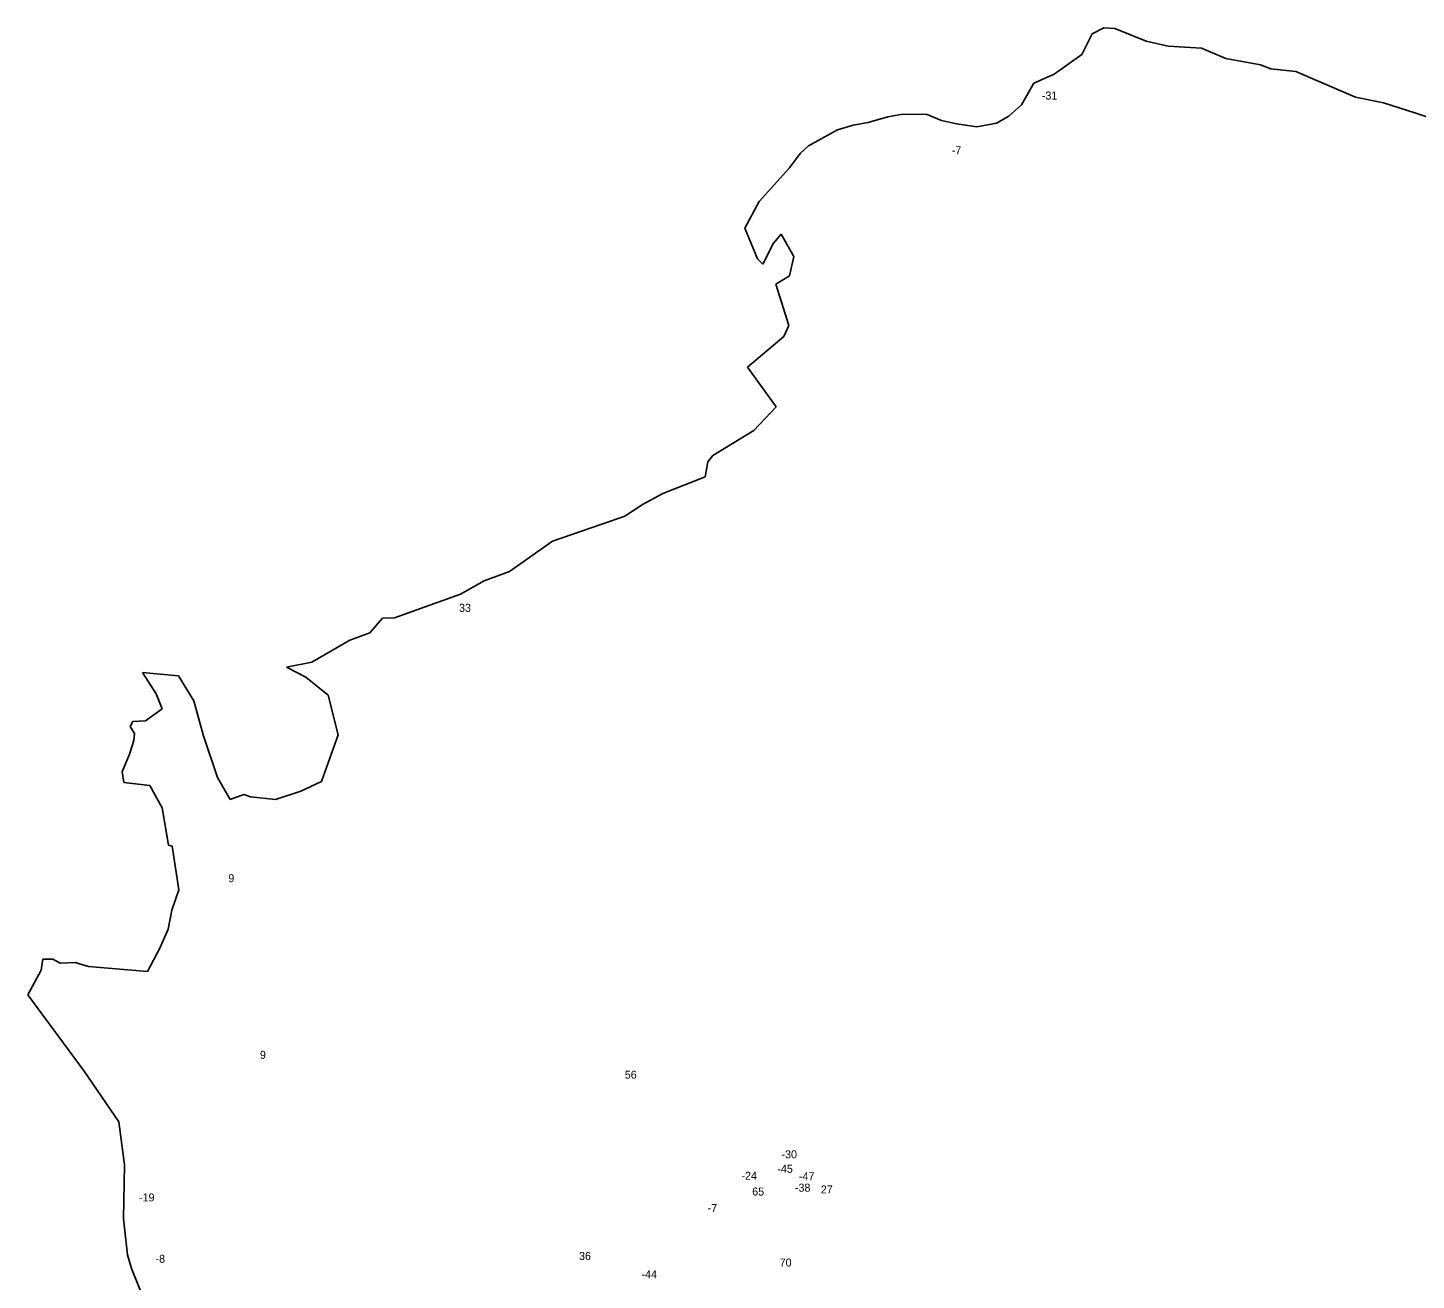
# Model space of a CAD drawing. Extents: x -788458 to -784980, y -976879 to -973650.
# Drawn here: x -788458 to -786723, y -975293 to -973728 of the extents above; entities that cross this region are included whole.
import ezdxf

# ---------------------------------------------------------------- set-up
doc = ezdxf.new("R2010")
doc.units = 0
for name, color, linetype in [('Vrstva 13', 7, 'Continuous'), ('Vrstva 24', 7, 'Continuous'), ('Vrstva 63', 7, 'Continuous')]:
    doc.layers.add(name, color=color, linetype=linetype)

msp = doc.modelspace()

# ---------------------------------------------------------------- linework, layer by layer
at = {"layer": 'Vrstva 13'}
for p, q in [((-787127.9, -973736.1), (-787113.3, -973728.4)), ((-787113.3, -973728.4), (-787099.4, -973729.3)), ((-787099.4, -973729.3), (-787060.2, -973745.3)), ((-787140.6, -973762), (-787127.9, -973736.1)), ((-787060.2, -973745.3), (-787032.7, -973751.5)), ((-787175.1, -973786.5), (-787140.6, -973762)), ((-787032.7, -973751.5), (-786991, -973754)), ((-786991, -973754), (-786960.6, -973766.9)), ((-786960.6, -973766.9), (-786917.4, -973774.9)), ((-786917.4, -973774.9), (-786904.4, -973779.9)), ((-786904.4, -973779.9), (-786873.2, -973783.2)), ((-787216.1, -973824.8), (-787200.5, -973797.6)), ((-787200.5, -973797.6), (-787175.1, -973786.5)), ((-786873.2, -973783.2), (-786798.7, -973815.3)), ((-786798.7, -973815.3), (-786763.8, -973822.3)), ((-787231.7, -973838.8), (-787216.1, -973824.8)), ((-786763.8, -973822.3), (-786724.6, -973834.8)), ((-787446.1, -973856.1), (-787426.5, -973850)), ((-787426.5, -973850), (-787407.8, -973846.9)), ((-787407.8, -973846.9), (-787383.2, -973839.8)), ((-787383.2, -973839.8), (-787364.7, -973836.5)), ((-787364.7, -973836.5), (-787334.1, -973836.9)), ((-787334.1, -973836.9), (-787316.2, -973844.2)), ((-787316.2, -973844.2), (-787297.1, -973848.6)), ((-787297.1, -973848.6), (-787271.7, -973852.1)), ((-787271.7, -973852.1), (-787247.1, -973847.5)), ((-787247.1, -973847.5), (-787231.7, -973838.8)), ((-786724.6, -973834.8), (-786642.6, -973862.7)), ((-787482.1, -973876), (-787446.1, -973856.1)), ((-787505.8, -973903.5), (-787492.7, -973885.6)), ((-787492.7, -973885.6), (-787482.1, -973876)), ((-787543.7, -973945.4), (-787505.8, -973903.5)), ((-787561.8, -973978.7), (-787543.7, -973945.4)), ((-787546, -974017), (-787561.8, -973978.7)), ((-787516.5, -973986.2), (-787526.1, -973997.4)), ((-787500.7, -974014.1), (-787516.5, -973986.2)), ((-787526.1, -973997.4), (-787539.4, -974023.7)), ((-787539.4, -974023.7), (-787546, -974017)), ((-787506.1, -974038.2), (-787500.7, -974014.1)), ((-787522.8, -974048.7), (-787506.1, -974038.2)), ((-787506.6, -974100.3), (-787522.8, -974048.7)), ((-787513.2, -974114), (-787506.6, -974100.3)), ((-787558.2, -974152.3), (-787513.2, -974114)), ((-787522.6, -974201.9), (-787558.2, -974152.3)), ((-787550.6, -974231.4), (-787522.6, -974201.9)), ((-787601.8, -974263), (-787550.6, -974231.4)), ((-787607.8, -974270.8), (-787601.8, -974263)), ((-787611.1, -974289.5), (-787607.8, -974270.8)), ((-787664.2, -974310.2), (-787611.1, -974289.5)), ((-787688.7, -974323.7), (-787664.2, -974310.2)), ((-787711.6, -974338.6), (-787688.7, -974323.7)), ((-787802, -974369.7), (-787740.6, -974348.6)), ((-787740.6, -974348.6), (-787711.6, -974338.6)), ((-787855.9, -974407.8), (-787802, -974369.7)), ((-787917.1, -974435.9), (-787887.3, -974419.3)), ((-787887.3, -974419.3), (-787855.9, -974407.8)), ((-787999.3, -974465.7), (-787917.1, -974435.9)), ((-788030.1, -974484.2), (-788014.5, -974466.1)), ((-788014.5, -974466.1), (-787999.3, -974465.7)), ((-788055.3, -974493.4), (-788030.1, -974484.2)), ((-788102.7, -974520.9), (-788055.3, -974493.4)), ((-788134.2, -974527.1), (-788102.7, -974520.9)), ((-788110.2, -974539.8), (-788134.2, -974527.1)), ((-788297.1, -974560.4), (-788314.2, -974534)), ((-788314.2, -974534), (-788269.2, -974537.9)), ((-788269.2, -974537.9), (-788250.1, -974569.4)), ((-788082.5, -974562.3), (-788110.2, -974539.8)), ((-788289.8, -974579.4), (-788297.1, -974560.4)), ((-788069.8, -974612), (-788082.5, -974562.3)), ((-788310.6, -974594.4), (-788289.8, -974579.4)), ((-788250.1, -974569.4), (-788238.4, -974611.8)), ((-788329.6, -974601.4), (-788326.3, -974595.2)), ((-788326.3, -974595.2), (-788310.6, -974594.4)), ((-788324.4, -974610), (-788329.6, -974601.4)), ((-788325.2, -974618.9), (-788324.4, -974610)), ((-788238.4, -974611.8), (-788220.7, -974665.1)), ((-788090.7, -974670.3), (-788069.8, -974612)), ((-788330.6, -974636), (-788325.2, -974618.9)), ((-788339.8, -974657.9), (-788330.6, -974636)), ((-788337.7, -974671.4), (-788339.8, -974657.9)), ((-788220.7, -974665.1), (-788204.7, -974692.4)), ((-788305, -974675.3), (-788337.7, -974671.4)), ((-788289.6, -974702.8), (-788305, -974675.3)), ((-788148.1, -974692.6), (-788116.3, -974682)), ((-788116.3, -974682), (-788090.7, -974670.3)), ((-788204.7, -974692.4), (-788187.8, -974686.2)), ((-788187.8, -974686.2), (-788179.3, -974689.1)), ((-788179.3, -974689.1), (-788148.1, -974692.6)), ((-788281.7, -974749.5), (-788289.6, -974702.8)), ((-788277.1, -974750.7), (-788281.7, -974749.5)), ((-788269, -974805.3), (-788277.1, -974750.7)), ((-788277.6, -974830.7), (-788269, -974805.3)), ((-788282.3, -974854.8), (-788277.6, -974830.7)), ((-788292.8, -974878.3), (-788282.3, -974854.8)), ((-788308.2, -974907.5), (-788292.8, -974878.3)), ((-788457.7, -974936.6), (-788441, -974905.8)), ((-788441, -974905.8), (-788439, -974892.1)), ((-788439, -974892.1), (-788426.5, -974892.1)), ((-788426.5, -974892.1), (-788417.3, -974897.1)), ((-788417.3, -974897.1), (-788398.6, -974896.2)), ((-788398.6, -974896.2), (-788381.9, -974901.2)), ((-788381.9, -974901.2), (-788308.2, -974907.5)), ((-788387.3, -975032), (-788457.7, -974936.6)), ((-788344, -975095.3), (-788387.3, -975032)), ((-788337, -975149), (-788344, -975095.3)), ((-788338.2, -975216.5), (-788337, -975149)), ((-788333.2, -975261.4), (-788338.2, -975216.5)), ((-788328.2, -975278.5), (-788333.2, -975261.4)), ((-788270, -975422.2), (-788328.2, -975278.5))]:
    msp.add_line(p, q, dxfattribs=at)

# ---------------------------------------------------------------- texts
at = {"layer": 'Vrstva 24'}
for s, p in [('-31', (-787190.6, -973818.1)), ('-7', (-787303.2, -973886.5)), ('33', (-787918.8, -974458.1)), ('56', (-787711.7, -975041.4)), ('-30', (-787515.9, -975140.9)), ('-45', (-787521.1, -975159)), ('-24', (-787566, -975167.7)), ('-47', (-787494.1, -975168.2)), ('-19', (-788318.7, -975194.7)), ('65', (-787552.5, -975187.4)), ('-38', (-787499.1, -975182.6)), ('-7', (-787608.2, -975208)), ('-8', (-788298, -975271.4)), ('70', (-787518.2, -975276.1)), ('-44', (-787690.8, -975290.8))]:
    msp.add_text(s, height=10, dxfattribs=at).set_placement(p)
at = {"layer": 'Vrstva 63'}
for s, p in [('9', (-788207.1, -974795.9)), ('9', (-788167.6, -975016.6)), ('27', (-787466.8, -975184.8)), ('36', (-787768.9, -975267.9))]:
    msp.add_text(s, height=10, dxfattribs=at).set_placement(p)

doc.saveas('drawing.dxf')
